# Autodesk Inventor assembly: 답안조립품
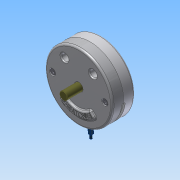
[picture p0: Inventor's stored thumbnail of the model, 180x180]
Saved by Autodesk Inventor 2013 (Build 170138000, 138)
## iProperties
Created: 2015-04
Part Number: 답안조립품
Document SubType Name: Assembly
Designer: Administrator
Author: Administrator
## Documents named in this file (10)
- C:\Users\Administrator\Desktop\450406V1027\답안조립품.iam
- C:\Users\Administrator\Desktop\450406V1027\본체.ipt
- C:\Users\Administrator\Desktop\450406V1027\축.ipt
- C:\Users\Administrator\Desktop\450406V1027\슬라이더2.ipt
- C:\Users\Administrator\Desktop\450406V1027\베어링62_22.ipt
- C:\Users\Administrator\Desktop\450406V1027\슬라이더.ipt
- C:\Users\Administrator\Desktop\450406V1027\평행핀.ipt
- C:\Users\Administrator\Desktop\450406V1027\멈춤링.ipt
- C:\Users\Administrator\Desktop\450406V1027\덮개.ipt
- C:\Users\Administrator\Desktop\450406V1027\M 10 x 35.ipt
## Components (2 placed, 1 different names)
1. M 10 x 35:1
2. M 10 x 35:2
